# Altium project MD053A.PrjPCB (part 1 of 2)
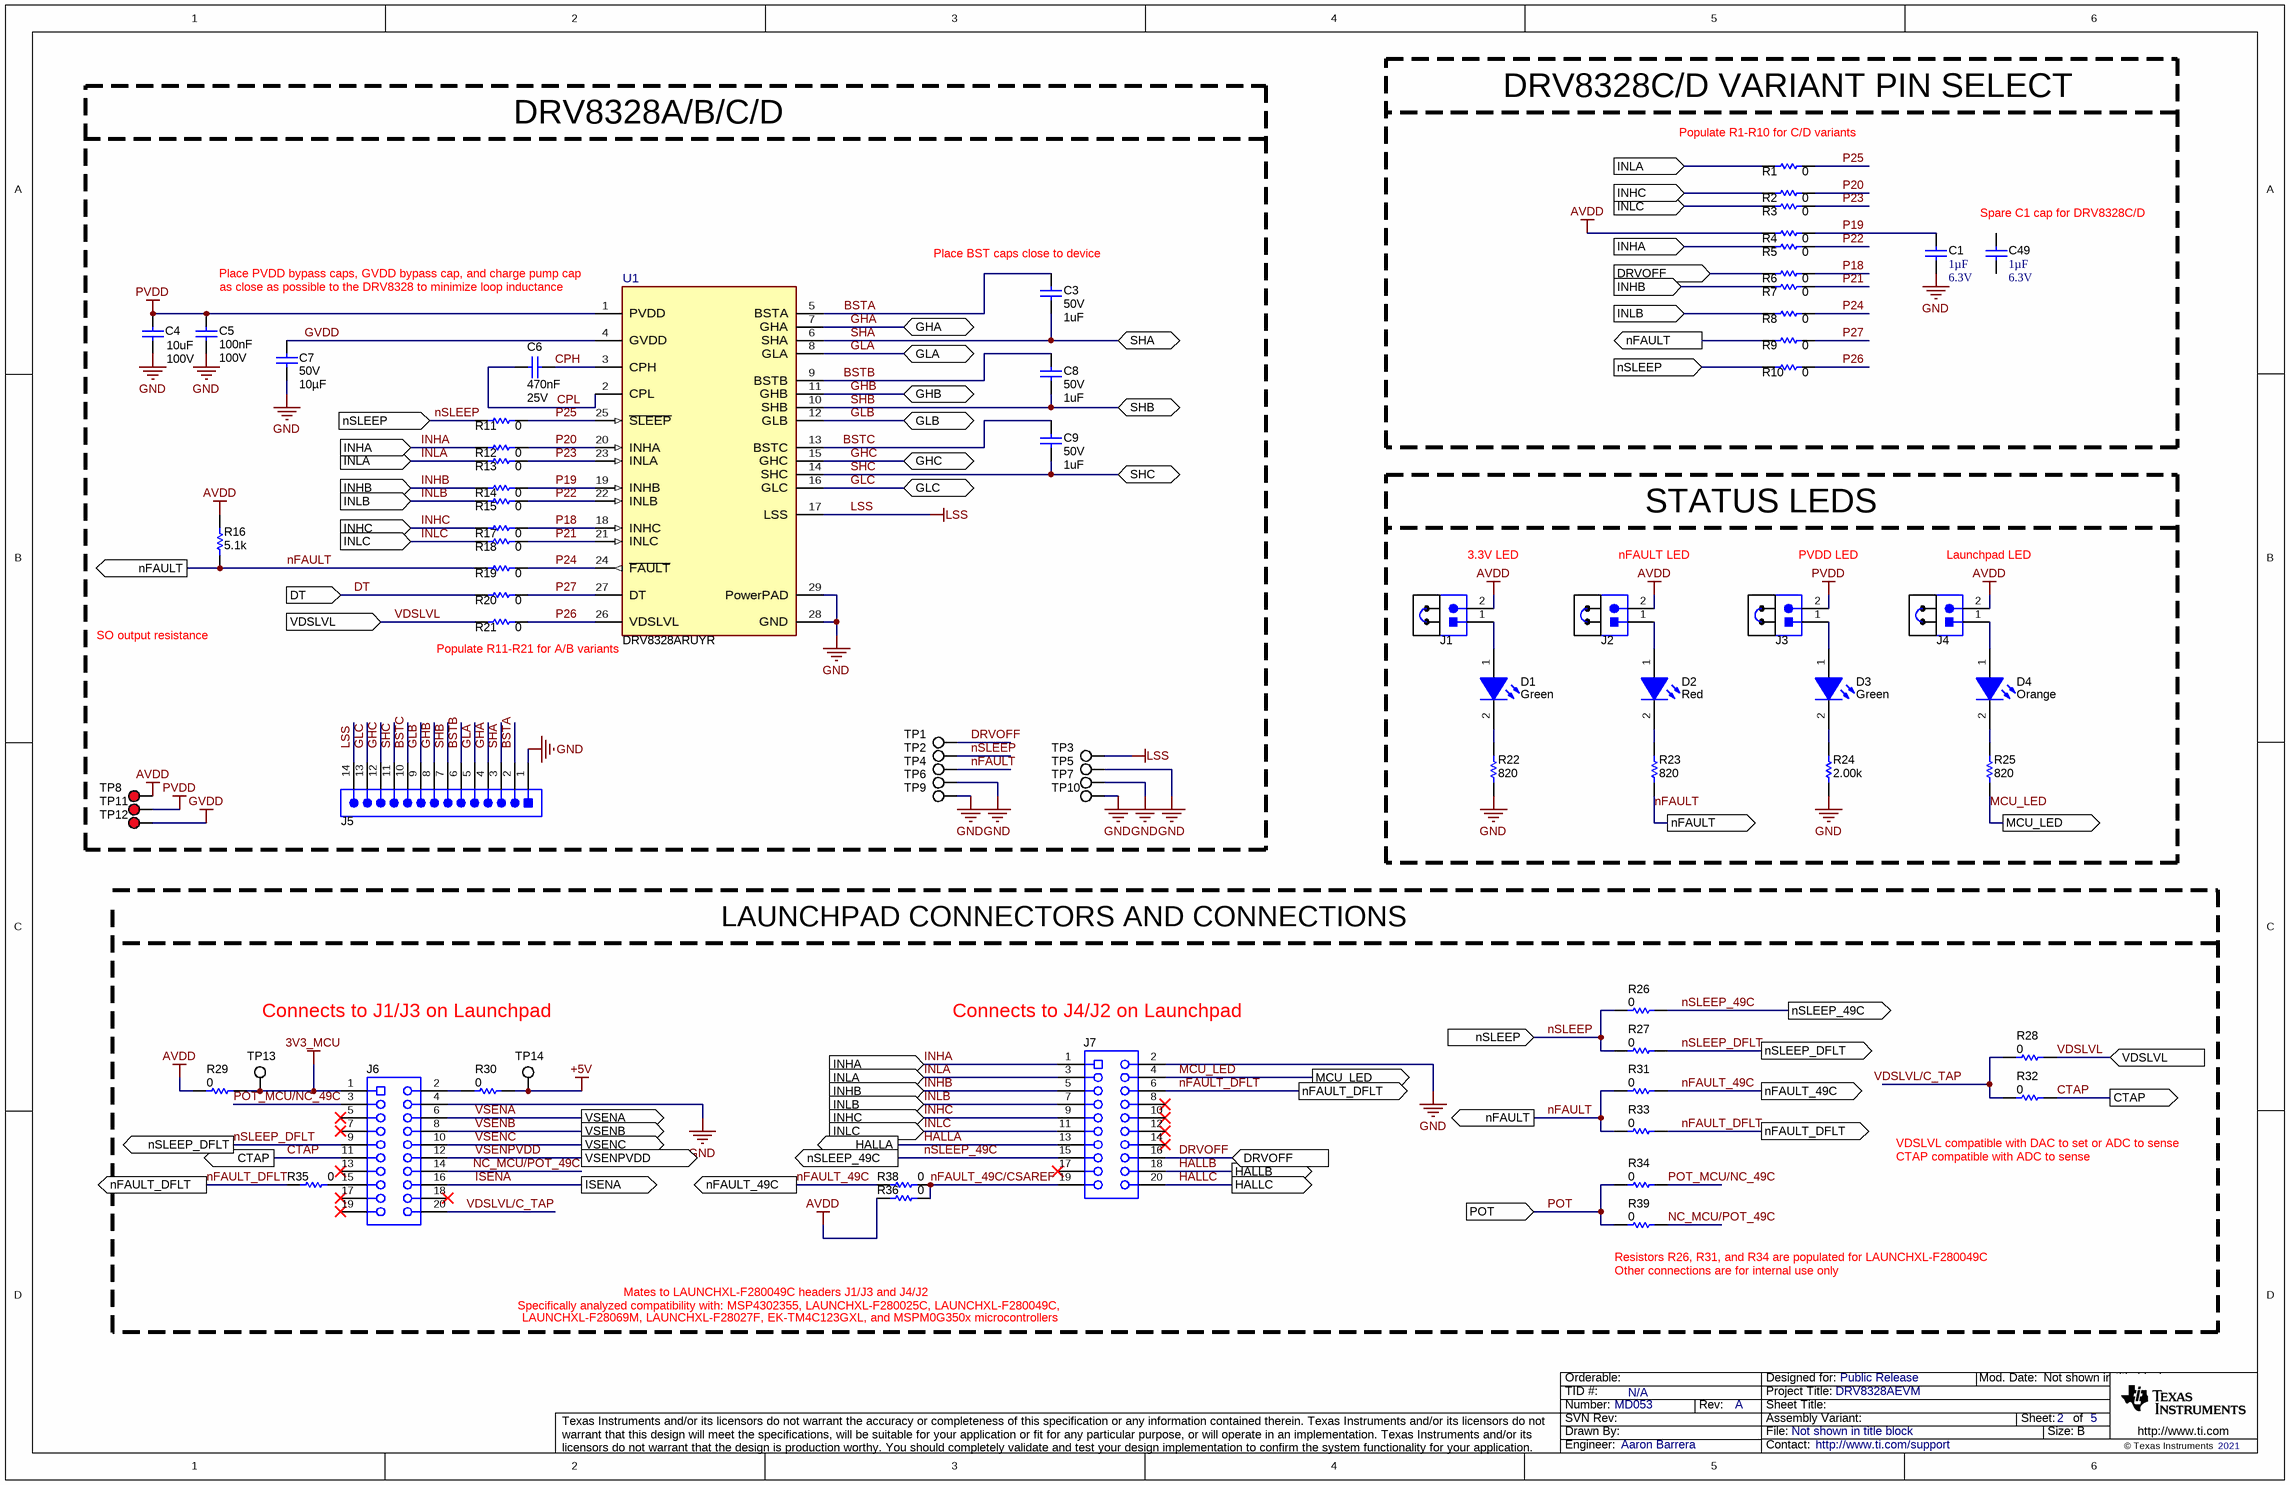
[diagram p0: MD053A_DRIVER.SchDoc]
CopyrightYear: 2021; PCB_Layout: Aaron Barrera; PCB_Rev: A; PRJ_Customer: Public Release; PRJ_Engineer: Aaron Barrera; PRJ_Number: MD053; PRJ_Title: DRV8328AEVM; SCH_Rev: A; TechSupport: http://www.ti.com/support; TID: N/A
5 sheets, 252 parts. Net scope: flat (ports and power ports of the same name join across sheets).
Board file: MD053A_PCB.PcbDoc
Sheets:
  MD053A_DRIVER.SchDoc
  MD053A_FETS_AND_POWER_STAGE.SchDoc
  MD053A_Hardware.SchDoc
  MD053A_LDO.SchDoc
  MD053A_POWER_AND_CONNECTORS.SchDoc

## Sheet MD053A_DRIVER.SchDoc
size 431 x 279 mm; Date: Not shown in title block; ApprovedBy: Not shown in title block; CheckedBy: Not shown in title block; Author: Not shown in title block; CompanyName: Not shown in title block; Engineer: Not shown in title block; Organization: Not shown in title block; Address1: Not shown in title block; Address2: Not shown in title block; Address3: Not shown in title block; Address4: Not shown in title block; DocumentNumber: 2; Revision: Use project parameter SCH_Rev; SheetNumber: 2; SheetTotal: 5; PageSetup: Record=PageOptions¦CenterHorizontal=True¦CenterVertical=True¦PrintScale=1.00¦XCorrection=1.00¦YCorrection=1.00¦PrintKind=0¦BorderSize=5000000¦LeftOffset=0¦BottomOffset=0¦Orientation=2¦PaperLength=1000¦PaperWidth=1000¦Scale=100¦PaperSource=15¦PrintQuality=600¦MediaType=1¦DitherType=10¦PaperKind=Letter¦PrintScaleMode=1

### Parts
C1  Cap_F: 1µF  VDC_V: 6.3V  [0603L]  (hidden comment: C0603C105K9RACAUTO)
C3  VDC_V: 50V  ValueDisplayed: 1uF  [0603L]  (hidden comment: C1608X5R1H105K080AB)
C4  VDC_V: 100V  ValueDisplayed: 10uF  [2220_280L]  (hidden comment: 22201C106MAT2A)
C5  Cap_F: 100nF  VDC_V: 100V  [0603L]  (hidden comment: GRM188R72A104KA35J)
C6  Cap_F: 470nF  VDC_V: 25V  [0603L]  (hidden comment: GRM188R71E474KA12D)
C7  VDC_V: 50V  ValueDisplayed: 10µF  [1206_190L]  (hidden comment: UMK316BBJ106KL-T)
C8  VDC_V: 50V  ValueDisplayed: 1uF  [0603L]  (hidden comment: C1608X5R1H105K080AB)
C9  VDC_V: 50V  ValueDisplayed: 1uF  [0603L]  (hidden comment: C1608X5R1H105K080AB)
C49  Cap_F: 1µF  VDC_V: 6.3V  [0603L]  (hidden comment: C0603C105K9RACAUTO)
D1  value Green  [LTST-C170KGKT_Green]  (hidden comment: LTST-C170KGKT)
D2  value Red  [LED_LTST-C170_Red]  (hidden comment: LTST-C170KRKT)
D3  value Green  [LTST-C170KGKT_Green]  (hidden comment: LTST-C170KGKT)
D4  value Orange  [LTST-C170KFKT_Orange]  (hidden comment: LTST-C170KFKT)
J1  TSW-102-07-G-S  [TSW-102-07-G-S]  (value not drawn)
J2  TSW-102-07-G-S  [TSW-102-07-G-S]  (value not drawn)
J3  TSW-102-07-G-S  [TSW-102-07-G-S]  (value not drawn)
J4  TSW-102-07-G-S  [TSW-102-07-G-S]  (value not drawn)
J5  TSW-114-07-G-S  [TSW-114-07-G-S]  (value not drawn)
J6  SSQ-110-03-G-D  [Samtec_SSQ-110-03-x-D]  (value not drawn)
J7  SSQ-110-03-G-D  [Samtec_SSQ-110-03-x-D]  (value not drawn)
R1  ValueDisplayed: 0  [0603L]  (hidden comment: ERJ-3GEY0R00V)
R2  ValueDisplayed: 0  [0603L]  (hidden comment: ERJ-3GEY0R00V)
R3  ValueDisplayed: 0  [0603L]  (hidden comment: ERJ-3GEY0R00V)
R4  ValueDisplayed: 0  [0603L]  (hidden comment: ERJ-3GEY0R00V)
R5  ValueDisplayed: 0  [0603L]  (hidden comment: ERJ-3GEY0R00V)
R6  ValueDisplayed: 0  [0603L]  (hidden comment: ERJ-3GEY0R00V)
R7  ValueDisplayed: 0  [0603L]  (hidden comment: ERJ-3GEY0R00V)
R8  ValueDisplayed: 0  [0603L]  (hidden comment: ERJ-3GEY0R00V)
R9  ValueDisplayed: 0  [0603L]  (hidden comment: ERJ-3GEY0R00V)
R10  ValueDisplayed: 0  [0603L]  (hidden comment: ERJ-3GEY0R00V)
R11  ValueDisplayed: 0  [0603L]  (hidden comment: ERJ-3GEY0R00V)
R12  ValueDisplayed: 0  [0603L]  (hidden comment: ERJ-3GEY0R00V)
R13  ValueDisplayed: 0  [0603L]  (hidden comment: ERJ-3GEY0R00V)
R14  ValueDisplayed: 0  [0603L]  (hidden comment: ERJ-3GEY0R00V)
R15  ValueDisplayed: 0  [0603L]  (hidden comment: ERJ-3GEY0R00V)
R16  ValueDisplayed: 5.1k  [0603L]  (hidden comment: CRCW06035K10JNEA)
R17  ValueDisplayed: 0  [0603L]  (hidden comment: ERJ-3GEY0R00V)
R18  ValueDisplayed: 0  [0603L]  (hidden comment: ERJ-3GEY0R00V)
R19  ValueDisplayed: 0  [0603L]  (hidden comment: ERJ-3GEY0R00V)
R20  ValueDisplayed: 0  [0603L]  (hidden comment: ERJ-3GEY0R00V)
R21  ValueDisplayed: 0  [0603L]  (hidden comment: ERJ-3GEY0R00V)
R22  ValueDisplayed: 820  [0603L]  (hidden comment: RC0603JR-07820RL)
R23  ValueDisplayed: 820  [0603L]  (hidden comment: RC0603JR-07820RL)
R24  ValueDisplayed: 2.00k  [0603L]  (hidden comment: RG1608P-202-B-T5)
R25  ValueDisplayed: 820  [0603L]  (hidden comment: RC0603JR-07820RL)
R26  ValueDisplayed: 0  [0603L]  (hidden comment: ERJ-3GEY0R00V)
R27  ValueDisplayed: 0  [0603L]  (hidden comment: ERJ-3GEY0R00V)
R28  ValueDisplayed: 0  [0603L]  (hidden comment: ERJ-3GEY0R00V)
R29  ValueDisplayed: 0  [0603L]  (hidden comment: ERJ-3GEY0R00V)
R30  ValueDisplayed: 0  [0603L]  (hidden comment: ERJ-3GEY0R00V)
R31  ValueDisplayed: 0  [0603L]  (hidden comment: ERJ-3GEY0R00V)
R32  ValueDisplayed: 0  [0603L]  (hidden comment: ERJ-3GEY0R00V)
R33  ValueDisplayed: 0  [0603L]  (hidden comment: ERJ-3GEY0R00V)
R34  ValueDisplayed: 0  [0603L]  (hidden comment: ERJ-3GEY0R00V)
R35  ValueDisplayed: 0  [0603L]  (hidden comment: ERJ-3GEY0R00V)
R36  ValueDisplayed: 0  [0603L]  (hidden comment: ERJ-3GEY0R00V)
R38  ValueDisplayed: 0  [0603L]  (hidden comment: ERJ-3GEY0R00V)
R39  ValueDisplayed: 0  [0603L]  (hidden comment: ERJ-3GEY0R00V)
SH-J1  SNT-100-BK-G  [SNT-100-BK-G]  (value not drawn)
SH-J2  SNT-100-BK-G  [SNT-100-BK-G]  (value not drawn)
SH-J3  SNT-100-BK-G  [SNT-100-BK-G]  (value not drawn)
SH-J4  SNT-100-BK-G  [SNT-100-BK-G]  (value not drawn)
TP1  DRVOFF  [Testpoint_Keystone_Miniature]  (value not drawn)
TP2  nSLEEP  [Testpoint_Keystone_Miniature]  (value not drawn)
TP3  LSS  [Testpoint_Keystone_Miniature]  (value not drawn)
TP4  nFAULT  [Testpoint_Keystone_Miniature]  (value not drawn)
TP5  GND  [Testpoint_Keystone_Miniature]  (value not drawn)
TP6  GND  [Testpoint_Keystone_Miniature]  (value not drawn)
TP7  GND  [Testpoint_Keystone_Miniature]  (value not drawn)
TP8  AVDD  [Keystone5000]  (value not drawn)
TP9  GND  [Testpoint_Keystone_Miniature]  (value not drawn)
TP10  GND  [Testpoint_Keystone_Miniature]  (value not drawn)
TP11  PVDD  [Keystone5000]  (value not drawn)
TP12  GVDD  [Keystone5000]  (value not drawn)
TP13  3V3_MCU  [Testpoint_Keystone_Miniature]  (value not drawn)
TP14  5V  [Testpoint_Keystone_Miniature]  (value not drawn)
U1  DRV8328ARUYR  [RUY0028A-MFG]

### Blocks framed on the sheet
DRV8328A/B/C/D: C3-C9 J5 R11-R21 TP1-TP12 U1
DRV8328C/D VARIANT PIN SELECT: C1 C49 R1-R10
STATUS LEDS: D1-D4 J1-J4 R22-R25 SH-J1-SH-J4

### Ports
CTAP (out), DRVOFF (in), DT (in), GHA (bidir), GHB (bidir), GHC (bidir), GLA (bidir), GLB (bidir), GLC (bidir), HALLA (out), HALLB (out), HALLC (out), INHA (in), INHB (in), INHC (in), INLA (in), INLB (in), INLC (in), ISENA (out), MCU_LED (out), nFAULT (out), nFAULT_49C (out), nFAULT_DFLT (out), nSLEEP (in), nSLEEP_49C (out), nSLEEP_DFLT (out), POT (in), SHA (bidir), SHB (bidir), SHC (bidir), VDSLVL (in), VSENA (out), VSENB (out), VSENC (out), VSENPVDD (out)

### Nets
3V3_MCU: J6.1 R29.2 TP13.1
+5V: R30.2 TP14.1
AVDD: J1.2 J2.2 J4.2 R4.1 R16.1 R29.1 R36.1 TP8.1
GND: C1.1 C4.2 C5.2 C7.2 J5.1 J6.4 J7.2 R22.1 R24.1 TP5.1 TP6.1 TP7.1 TP9.1 TP10.1 U1.28(GND) U1.29(PowerPAD)
GVDD: C7.1 TP12.1 U1.4(GVDD)
LSS: J5.14 TP3.1 U1.17(LSS)
PVDD: C4.1 C5.1 J3.2 TP11.1 U1.1(PVDD)
BSTA: C3.1 J5.2 U1.5(BSTA)
BSTB: C8.1 J5.6 U1.9(BSTB)
BSTC: C9.1 J5.10 U1.13(BSTC)
CPH: C6.1 U1.3(CPH)
CPL: C6.2 U1.2(CPL)
CTAP: J6.11 R32.2 ; port CTAP
DRVOFF: J7.16 R6.1 TP1.1 ; port DRVOFF
DT: R20.1 ; port DT
GHA: J5.4 U1.7(GHA) ; port GHA
GHB: J5.8 U1.11(GHB) ; port GHB
GHC: J5.12 U1.15(GHC) ; port GHC
GLA: J5.5 U1.8(GLA) ; port GLA
GLB: J5.9 U1.12(GLB) ; port GLB
GLC: J5.13 U1.16(GLC) ; port GLC
HALLA: J7.13 ; port HALLA
HALLB: J7.18 ; port HALLB
HALLC: J7.20 ; port HALLC
INHA: J7.1 R5.1 R12.1 ; port INHA
INHB: J7.5 R7.1 R14.1 ; port INHB
INHC: J7.9 R2.1 R17.1 ; port INHC
INLA: J7.3 R1.1 R13.1 ; port INLA
INLB: J7.7 R8.1 R15.1 ; port INLB
INLC: J7.11 R3.1 R18.1 ; port INLC
ISENA: J6.16 ; port ISENA
MCU_LED: J7.4 R25.1 ; port MCU_LED
NC_MCU/POT_49C: J6.14 R39.2
nFAULT: R9.1 R16.2 R19.1 R23.1 R31.1 R33.1 TP4.1 ; port nFAULT
nFAULT_49C: R31.2 R38.1 ; port nFAULT_49C
nFAULT_49C/CSAREF: J7.19 R36.2 R38.2
nFAULT_DFLT: J7.6 R33.2 R35.1 ; port nFAULT_DFLT
nSLEEP: R10.1 R11.1 R26.1 R27.1 TP2.1 ; port nSLEEP
nSLEEP_49C: J7.15 R26.2 ; port nSLEEP_49C
nSLEEP_DFLT: J6.9 R27.2 ; port nSLEEP_DFLT
P18: R6.2 R17.2 U1.18(INHC)
P19: C1.2 R4.2 R14.2 U1.19(INHB)
P20: R2.2 R12.2 U1.20(INHA)
P21: R7.2 R18.2 U1.21(INLC)
P22: R5.2 R15.2 U1.22(INLB)
P23: R3.2 R13.2 U1.23(INLA)
P24: R8.2 R19.2 U1.24(~{FAULT})
P25: R1.2 R11.2 U1.25(~{SLEEP})
P26: R10.2 R21.2 U1.26(VDSLVL)
P27: R9.2 R20.2 U1.27(DT)
POT: R34.1 R39.1 ; port POT
POT_MCU/NC_49C: J6.3 R34.2
SHA: C3.2 J5.3 U1.6(SHA) ; port SHA
SHB: C8.2 J5.7 U1.10(SHB) ; port SHB
SHC: C9.2 J5.11 U1.14(SHC) ; port SHC
VDSLVL: R21.1 R28.2 ; port VDSLVL
VDSLVL/C_TAP: J6.20 R28.1 R32.1
VSENA: J6.6 ; port VSENA
VSENB: J6.8 ; port VSENB
VSENC: J6.10 ; port VSENC
VSENPVDD: J6.12 ; port VSENPVDD
NetD1_1: D1.1(A) J1.1
NetD1_2: D1.2(K) R22.2
NetD2_1: D2.1(A) J2.1
NetD2_2: D2.2(K) R23.2
NetD3_1: D3.1(A) J3.1
NetD3_2: D3.2(K) R24.2
NetD4_1: D4.1(A) J4.1
NetD4_2: D4.2(K) R25.2
NetJ6_2: J6.2 R30.1
NetJ6_15: J6.15 R35.2

Not connected (* = marked no-connect by the designer): C49 1 2; J6 5* 7* 13* 17* 18* 19*; J7 8* 10* 12* 14* 17*

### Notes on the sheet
- (near R1) Populate R1-R10 for C/D variants
- (near C49) Spare C1 cap for DRV8328C/D
- as close as possible to the DRV8328 to minimize loop inductance
- Place PVDD bypass caps, GVDD bypass cap, and charge pump cap
- (near C3) Place BST caps close to device
- 3.3V LED
- nFAULT LED
- PVDD LED
- Launchpad LED
- SO output resistance
- Populate R11-R21 for A/B variants
- LAUNCHPAD CONNECTORS AND CONNECTIONS
- Connects to J1/J3 on Launchpad
- (near J7) Connects to J4/J2 on Launchpad
- (near R32) VDSLVL compatible with DAC to set or ADC to sense
- CTAP compatible with ADC to sense
- Mates to LAUNCHXL-F280049C headers J1/J3 and J4/J2
- Specifically analyzed compatibility with: MSP4302355, LAUNCHXL-F280025C, LAUNCHXL-F280049C,
- (near R39) Resistors R26, R31, and R34 are populated for LAUNCHXL-F280049C
- (near R39) Other connections are for internal use only
- LAUNCHXL-F28069M, LAUNCHXL-F28027F, EK-TM4C123GXL, and MSPM0G350x microcontrollers

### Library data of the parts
C1 C49 = CMP-0086190-1: CAP, CERM, 1 µF, 6.3 V,+/- 10%, X7R, AEC-Q200 Grade 1, 0603; Manufacturer: Kemet; SizeArea_mm2: 1.28; Cap_Case: 0603; SizeY_mm: 0.8; AEC Category: Q200; AEC Qualified: Y; TaMax_C: 125°C; SizeZ_mm: 1; SizeX_mm: 1.6; Polarized: N; Value: 1uF; SizeAreaWB_mm2: 4.68; TaMin_C: -55°C; U/M: EA
C3 C8 C9 = CMP-0007011-4: CAP, CERM, 1 uF, 50 V, +/- 10%, X5R, 0603; Manufacturer: TDK; TaMin_C: -55°C; ESR_ohm: 5.522m; Polarized: N; SizeAreaWB_mm2: 4.68; Value1: 0.005522 ohm; U/M: EA; Value: 1uF; TaMax_C: 85°C; SizeZ_mm: 1; SizeX_mm: 1.6; SizeY_mm: 0.8; Cap_Case: 0603; SizeArea_mm2: 1.28; Cap_F: 1µF; IRMS_A: 2.21617A; AEC Category: Q200
C4 = CMP-0009304-2: CAP, CERM, 10 uF, 100 V, +/- 20%, X7R, 2220; Manufacturer: AVX; TaMin_C: -55°C; Polarized: N; SizeAreaWB_mm2: 53.9; Value1: Unknown; U/M: EA; Value: 10uF; TaMax_C: 125°C; SizeZ_mm: 2.8; SizeX_mm: 5.7; SizeY_mm: 5; Cap_Case: 2220; SizeArea_mm2: 28.5; Cap_F: 10µF; AEC Category: Q200
C5 = CMP-0007470-5: CAP, CERM, 0.1 uF, 100 V, +/- 10%, X7R, 0603; Manufacturer: MuRata; TaMin_C: -55°C; Polarized: N; SizeAreaWB_mm2: 4.68; Value1: Unknown; U/M: EA; Value: 0.1uF; TaMax_C: 125°C; SizeZ_mm: 1; SizeX_mm: 1.6; SizeY_mm: 0.8; Cap_Case: 0603; SizeArea_mm2: 1.28; AEC Category: Q200
C6 = CMP-0007424-3: CAP, CERM, 0.47 uF, 25 V, +/- 10%, X7R, 0603; Manufacturer: MuRata; TaMin_C: -55°C; Polarized: N; SizeAreaWB_mm2: 4.68; Value1: Unknown; U/M: EA; Value: 0.47uF; TaMax_C: 125°C; SizeZ_mm: 1; SizeX_mm: 1.6; SizeY_mm: 0.8; Cap_Case: 0603; SizeArea_mm2: 1.28; AEC Category: Q200
C7 = CMP-0086153-1: CAP, CERM, 10 µF, 50 V,+/- 10%, X5R, 1206; Manufacturer: Taiyo Yuden; Polarized: N; SizeX_mm: 3.2; TaMax_C: 85°C; SizeY_mm: 1.6; AEC Category: Q200; SizeArea_mm2: 5.12; Cap_Case: 1206; SizeAreaWB_mm2: 10.92; TaMin_C: -55°C; SizeZ_mm: 1.9; U/M: EA; Value: 10uF
D1 D3 = CMP-0002888-2: LED, Green, SMD; Manufacturer: Lite-On; Io_A: 20mA; Value1: W; Vf_V: 2V; Type: AlInGaP
D2 = CMP-0002829-3: LED, Red, SMD; Manufacturer: Lite-On; Io_A: 20mA; SizeAreaWB_mm2: 6.75; Value1: W; SizeZ_mm: 1.2; SizeX_mm: 2; SizeY_mm: 1.25; Vf_V: 2V; SizeArea_mm2: 2.5; Type: AlInGaP
D4 = CMP-0002890-1: LED, Orange, SMD; Manufacturer: Lite-On; Io_A: 20mA; Value1: W; U/M: EA; Vf_V: 2V; Type: AlInGaP
J1-J4 = CMP-0075405-3: Header, 100mil, 2x1, Gold, TH; Manufacturer: Samtec; Current_A: 6.3A; Green_Lifecycle: Active; Pitch_mm: 2.54; Cert_CSA: Y; Cert_VDE: N; Green_REACh: Passed; Row_Count: 1; Gender: Male; Voltage_V: 550V
J5 = CMP-0075428-1: Header, 100mil, 14x1, Gold, TH; Manufacturer: Samtec; Pitch_mm: 2.54; Cert_VDE: N; Gender: Male; Cert_CSA: Y; Voltage_V: 550V; Green_REACh: Passed; Current_A: 6.3A; CT: False; Green_Lifecycle: Active; Row_Count: 1; CNHeader: True
J6 J7 = CMP-0075613-1: Receptacle, 2.54mm, 10x2, Gold, TH; Manufacturer: Samtec; Pitch_mm: 2.54; Cert_VDE: N; Gender: Female; Cert_CSA: Y; Current_A: 6.3A; Voltage_V: 550V; CT: True; Row_Count: 2; CompType: Socket Strip; CNHeader: False
R1-R15 R17-R21 R26-R36 R38 R39 = CMP-0025874-4: RES, 0, 5%, 0.1 W, AEC-Q200 Grade 0, 0603; Manufacturer: Panasonic; Power_W: 100mW; TempCo: 600 ppm/C; Value_Code: 0000; Value: 0; EIA_Code: E24; SizeX_mm: 1.6; SizeY_mm: 0.8; SizeZ_mm: 1; Value2: 0.1W; SizeArea_mm2: 1.28; AEC Qualified: Y; VDC_V: 50V; AEC Category: Q200; SizeAreaWB_mm2: 4.68
R16 = CMP-0025830-4: RES, 5.1 k, 5%, 0.1 W, AEC-Q200 Grade 0, 0603; Manufacturer: Vishay-Dale; Power_W: 100mW; TempCo: 200 ppm/C; Value_Code: 5k10; Value: 5.1k; EIA_Code: E24; SizeX_mm: 1.6; SizeY_mm: 0.8; SizeZ_mm: 1; Value2: 0.1W; SizeArea_mm2: 1.28; AEC Qualified: Y; VDC_V: 75V; AEC Category: Q200; AEC Grade: 0
R22 R23 R25 = CMP-0025941-5: RES, 820, 5%, 0.1 W, 0603; Manufacturer: Yageo; Power_W: 100mW; TempCo: 100 ppm/C; Value_Code: 820R; Value: 820; EIA_Code: E24; SizeX_mm: 1.6; SizeY_mm: 0.8; SizeZ_mm: 1; Value2: 0.1W; SizeArea_mm2: 1.28; AEC Qualified: N; VDC_V: 75V; AEC Category: Q200; SizeAreaWB_mm2: 4.68
R24 = CMP-0023463-3: RES, 2.00 k, 0.1%, 0.1 W, 0603; Manufacturer: Susumu Co Ltd; Power_W: 100mW; TempCo: 25 ppm/C; Value_Code: 2k00; U/M: EA; Value: 2.00k; EIA_Code: E192; Res_ohm: 2k; SizeX_mm: 1.6; SizeY_mm: 0.8; SizeZ_mm: 1; Value2: 0.1W; SizeArea_mm2: 1.28; VDC_V: 75V; AEC Category: Q200
SH-J1-SH-J4 = CMP-0003623-3: Shunt, 100mil, Gold plated, Black; Alternate PartNumber: 969102-0000-DA; Manufacturer: Samtec; Alternate Manufacturer: 3M; Value: 1x2
TP1-TP7 TP9 TP10 TP13 TP14 = CMP-0055152-1: Test Point, Miniature, SMT; Manufacturer: Keystone; CNHeader: FALSE; Green_Lifecycle: Active; Green_REACh: Passed; CT: TRUE
TP8 TP11 TP12 = CMP-0055137-1: Test Point, Miniature, Red, TH; PartNumber: 5000; Manufacturer: Keystone; ContactFinish: Silver; CNHeader: FALSE; CT: TRUE; Green_Lifecycle: Active; Green_REACh: Passed
U1 = CMP-0091885-1: Three-Phase BLDC Gate Driver; Manufacturer: Texas Instruments; AEC Qualified: No; Switching Frequency: 200kHz; Min Supply Voltage: 4.5V; Motor Type: Brushless DC; Nominal Supply Current: 4-5mA; Number Of Outputs: 3; SizeZ_mm: 0.8mm; TaMin_C: -40°C; TJmax_C: +150°C; Max Supply Voltage: 60V; TaMax_C: +125°C; Standoff Height: 0mm

## Sheet MD053A_FETS_AND_POWER_STAGE.SchDoc
size 431 x 279 mm; Date: Not shown in title block; ApprovedBy: Not shown in title block; CheckedBy: Not shown in title block; Author: Not shown in title block; CompanyName: Not shown in title block; Engineer: Not shown in title block; Organization: Not shown in title block; Address1: Not shown in title block; Address2: Not shown in title block; Address3: Not shown in title block; Address4: Not shown in title block; DocumentNumber: 3; Revision: Use project parameter SCH_Rev; SheetNumber: 3; SheetTotal: 5; PageSetup: Record=PageOptions¦CenterHorizontal=True¦CenterVertical=True¦PrintScale=1.00¦XCorrection=1.00¦YCorrection=1.00¦PrintKind=0¦BorderSize=5000000¦LeftOffset=0¦BottomOffset=0¦Orientation=2¦PaperLength=1000¦PaperWidth=1000¦Scale=100¦PaperSource=15¦PrintQuality=600¦MediaType=1¦DitherType=10¦PaperKind=Letter¦PrintScaleMode=1
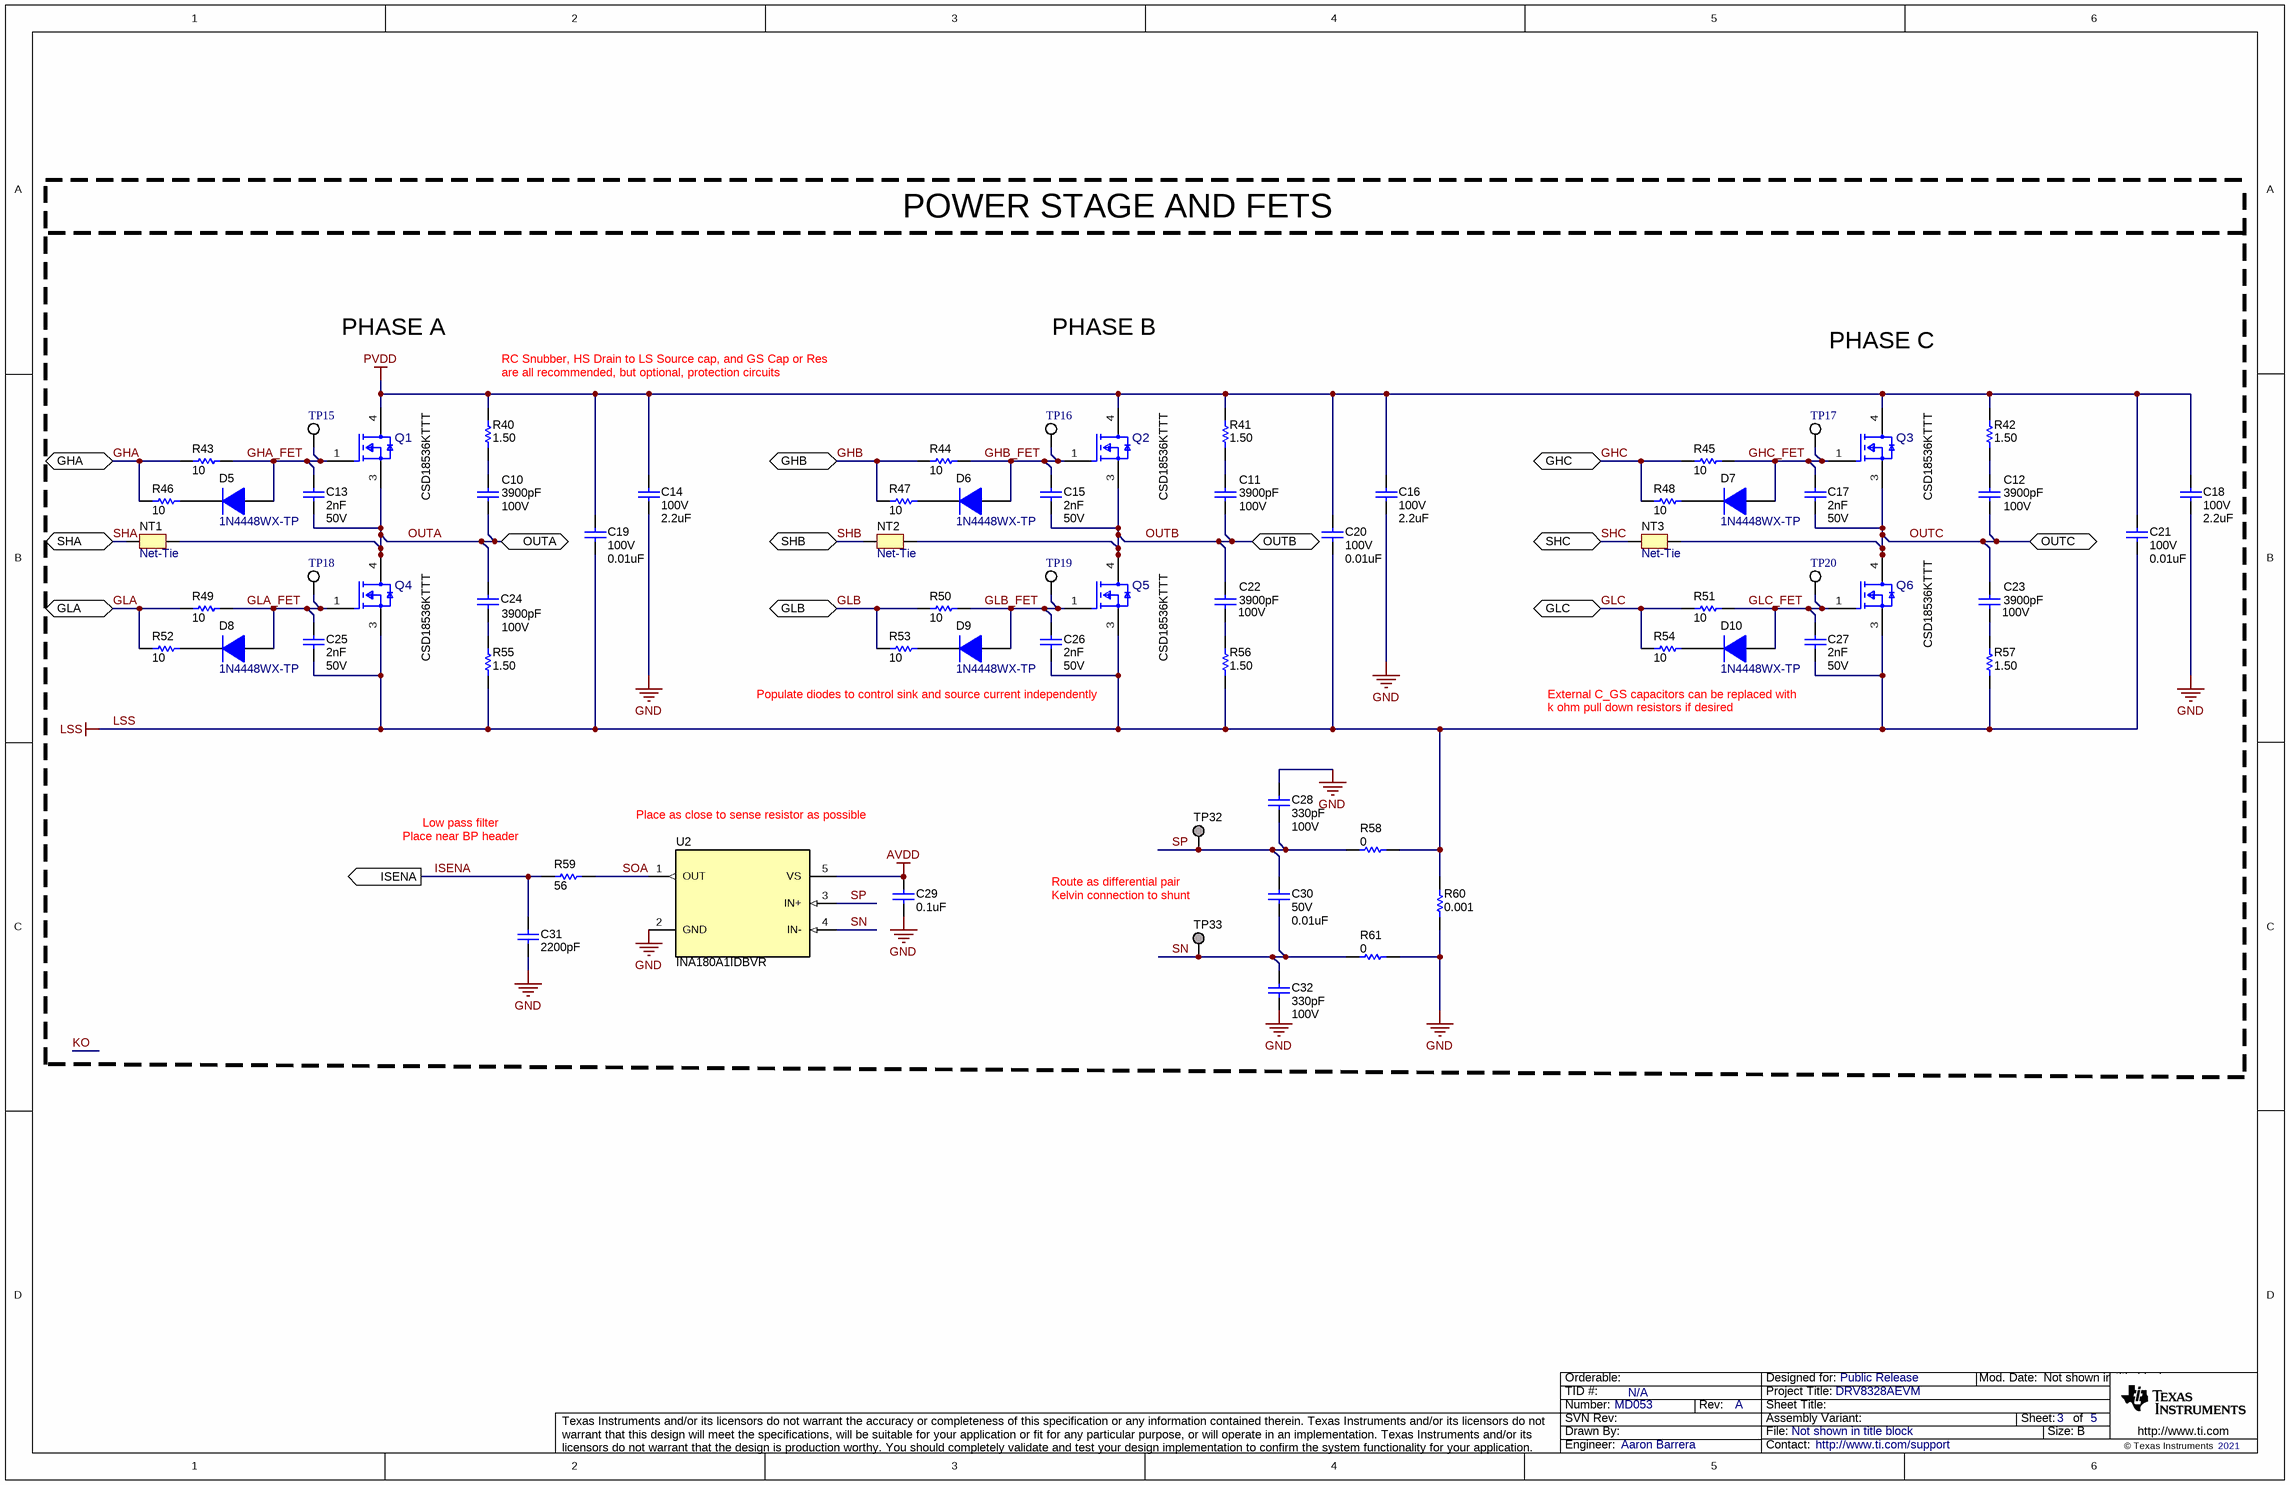
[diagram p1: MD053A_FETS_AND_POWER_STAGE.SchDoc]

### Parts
C10  VDC_V: 100V  ValueDisplayed: 3900pF  [1206L]  (hidden comment: 12061C392KAZ2A)
C11  VDC_V: 100V  ValueDisplayed: 3900pF  [1206L]  (hidden comment: 12061C392KAZ2A)
C12  VDC_V: 100V  ValueDisplayed: 3900pF  [1206L]  (hidden comment: 12061C392KAZ2A)
C13  Cap_F: 2nF  VDC_V: 50V  [0603L]  (hidden comment: GRM188R71H202KA01D)  (no BOM)
C14  VDC_V: 100V  ValueDisplayed: 2.2uF  [1210_210L]  (hidden comment: C1210C225K1RACTU)
C15  Cap_F: 2nF  VDC_V: 50V  [0603L]  (hidden comment: GRM188R71H202KA01D)  (no BOM)
C16  VDC_V: 100V  ValueDisplayed: 2.2uF  [1210_210L]  (hidden comment: C1210C225K1RACTU)
C17  Cap_F: 2nF  VDC_V: 50V  [0603L]  (hidden comment: GRM188R71H202KA01D)  (no BOM)
C18  VDC_V: 100V  ValueDisplayed: 2.2uF  [1210_210L]  (hidden comment: C1210C225K1RACTU)
C19  VDC_V: 100V  ValueDisplayed: 0.01uF  [0805L]  (hidden comment: 08051C103JAT2A)
C20  VDC_V: 100V  ValueDisplayed: 0.01uF  [0805L]  (hidden comment: 08051C103JAT2A)
C21  VDC_V: 100V  ValueDisplayed: 0.01uF  [0805L]  (hidden comment: 08051C103JAT2A)
C22  VDC_V: 100V  ValueDisplayed: 3900pF  [1206L]  (hidden comment: 12061C392KAZ2A)
C23  VDC_V: 100V  ValueDisplayed: 3900pF  [1206L]  (hidden comment: 12061C392KAZ2A)
C24  VDC_V: 100V  ValueDisplayed: 3900pF  [1206L]  (hidden comment: 12061C392KAZ2A)
C25  Cap_F: 2nF  VDC_V: 50V  [0603L]  (hidden comment: GRM188R71H202KA01D)  (no BOM)
C26  Cap_F: 2nF  VDC_V: 50V  [0603L]  (hidden comment: GRM188R71H202KA01D)  (no BOM)
C27  Cap_F: 2nF  VDC_V: 50V  [0603L]  (hidden comment: GRM188R71H202KA01D)  (no BOM)
C28  Cap_F: 330pF  VDC_V: 100V  [0603L]  (hidden comment: 06031C331KAT2A)
C29  ValueDisplayed: 0.1uF  [0603L]  (hidden comment: C0603C104J4RACTU)
C30  VDC_V: 50V  ValueDisplayed: 0.01uF  [0603L]  (hidden comment: C1608NP01H103J080AA)
C31  ValueDisplayed: 2200pF  [0603L]  (hidden comment: GRM188R71C222KA01D)
C32  Cap_F: 330pF  VDC_V: 100V  [0603L]  (hidden comment: 06031C331KAT2A)
D5  1N4448WX-TP  [SOD-323]
D6  1N4448WX-TP  [SOD-323]
D7  1N4448WX-TP  [SOD-323]
D8  1N4448WX-TP  [SOD-323]
D9  1N4448WX-TP  [SOD-323]
D10  1N4448WX-TP  [SOD-323]
NT1  Net-Tie  [NetTie_0603]  (net tie, no BOM)
NT2  Net-Tie  [NetTie_0603]  (net tie, no BOM)
NT3  Net-Tie  [NetTie_0603]  (net tie, no BOM)
Q1  CSD18536KTTT  [KTT0002A-MFG]
Q2  CSD18536KTTT  [KTT0002A-MFG]
Q3  CSD18536KTTT  [KTT0002A-MFG]
Q4  CSD18536KTTT  [KTT0002A-MFG]
Q5  CSD18536KTTT  [KTT0002A-MFG]
Q6  CSD18536KTTT  [KTT0002A-MFG]
R40  ValueDisplayed: 1.50  [1206L]  (hidden comment: CRCW12061R50FKEA)
R41  ValueDisplayed: 1.50  [1206L]  (hidden comment: CRCW12061R50FKEA)
R42  ValueDisplayed: 1.50  [1206L]  (hidden comment: CRCW12061R50FKEA)
R43  ValueDisplayed: 10  [0603L]  (hidden comment: CRCW060310R0JNEA)
R44  ValueDisplayed: 10  [0603L]  (hidden comment: CRCW060310R0JNEA)
R45  ValueDisplayed: 10  [0603L]  (hidden comment: CRCW060310R0JNEA)
R46  ValueDisplayed: 10  [0603L]  (hidden comment: CRCW060310R0JNEA)
R47  ValueDisplayed: 10  [0603L]  (hidden comment: CRCW060310R0JNEA)
R48  ValueDisplayed: 10  [0603L]  (hidden comment: CRCW060310R0JNEA)
R49  ValueDisplayed: 10  [0603L]  (hidden comment: CRCW060310R0JNEA)
R50  ValueDisplayed: 10  [0603L]  (hidden comment: CRCW060310R0JNEA)
R51  ValueDisplayed: 10  [0603L]  (hidden comment: CRCW060310R0JNEA)
R52  ValueDisplayed: 10  [0603L]  (hidden comment: CRCW060310R0JNEA)
R53  ValueDisplayed: 10  [0603L]  (hidden comment: CRCW060310R0JNEA)
R54  ValueDisplayed: 10  [0603L]  (hidden comment: CRCW060310R0JNEA)
R55  ValueDisplayed: 1.50  [1206L]  (hidden comment: CRCW12061R50FKEA)
R56  ValueDisplayed: 1.50  [1206L]  (hidden comment: CRCW12061R50FKEA)
R57  ValueDisplayed: 1.50  [1206L]  (hidden comment: CRCW12061R50FKEA)
R58  ValueDisplayed: 0  [0603L]  (hidden comment: ERJ-3GEY0R00V)
R59  value 56  [0603L]  (hidden comment: CRCW060356R0JNEA)
R60  ValueDisplayed: 0.001  [CSS2725_001]  (hidden comment: CSS2725FT1L00)
R61  ValueDisplayed: 0  [0603L]  (hidden comment: ERJ-3GEY0R00V)
TP15  GHA_FET  [Testpoint_Keystone_Miniature]  (value not drawn)
TP16  GHB_FET  [Testpoint_Keystone_Miniature]  (value not drawn)
TP17  GHC_FET  [Testpoint_Keystone_Miniature]  (value not drawn)
TP18  GLA_FET  [Testpoint_Keystone_Miniature]  (value not drawn)
TP19  GLB_FET  [Testpoint_Keystone_Miniature]  (value not drawn)
TP20  GLC_FET  [Testpoint_Keystone_Miniature]  (value not drawn)
TP32  SP  [TP_SM_1MM]  (value not drawn)  (no BOM)
TP33  SN  [TP_SM_1MM]  (value not drawn)  (no BOM)
U2  INA180A1IDBVR  [DBV0005A_N]

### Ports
GHA (bidir), GHB (bidir), GHC (bidir), GLA (bidir), GLB (bidir), GLC (bidir), ISENA (out), OUTA (bidir), OUTB (bidir), OUTC (bidir), SHA (bidir), SHB (bidir), SHC (bidir)

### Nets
AVDD: C29.1 U2.5(VS)
GND: C14.2 C16.2 C18.2 C28.1 C29.2 C31.2 C32.2 R60.1 R61.2 U2.2(GND)
LSS: C19.2 C20.2 C21.2 C25.2 C26.2 C27.2 Q4.3(Source) Q5.3(Source) Q6.3(Source) R55.1 R56.1 R57.1 R58.2 R60.2
PVDD: C14.1 C16.1 C18.1 C19.1 C20.1 C21.1 Q1.4(Drain) Q2.4(Drain) Q3.4(Drain) R40.1 R41.1 R42.1
GHA: R43.1 R46.1 ; port GHA
GHA_FET: C13.1 D5.2(A) Q1.1(Gate) R43.2 TP15.1
GHB: R44.1 R47.1 ; port GHB
GHB_FET: C15.1 D6.2(A) Q2.1(Gate) R44.2 TP16.1
GHC: R45.1 R48.1 ; port GHC
GHC_FET: C17.1 D7.2(A) Q3.1(Gate) R45.2 TP17.1
GLA: R49.1 R52.1 ; port GLA
GLA_FET: C25.1 D8.2(A) Q4.1(Gate) R49.2 TP18.1
GLB: R50.1 R53.1 ; port GLB
GLB_FET: C26.1 D9.2(A) Q5.1(Gate) R50.2 TP19.1
GLC: R51.1 R54.1 ; port GLC
GLC_FET: C27.1 D10.2(A) Q6.1(Gate) R51.2 TP20.1
ISENA: C31.1 R59.1 ; port ISENA
OUTA: C10.1 C13.2 C24.1 NT1.2 Q1.3(Source) Q4.4(Drain) ; port OUTA
OUTB: C11.1 C15.2 C22.1 NT2.2 Q2.3(Source) Q5.4(Drain) ; port OUTB
OUTC: C12.1 C17.2 C23.1 NT3.2 Q3.3(Source) Q6.4(Drain) ; port OUTC
SHA: NT1.1 ; port SHA
SHB: NT2.1 ; port SHB
SHC: NT3.1 ; port SHC
SN: C30.2 C32.1 R61.1 TP33.1 U2.4(IN-)
SOA: R59.2 U2.1(OUT)
SP: C28.2 C30.1 R58.1 TP32.1 U2.3(IN+)
NetC10_2: C10.2 R40.2
NetC11_2: C11.2 R41.2
NetC12_2: C12.2 R42.2
NetC22_2: C22.2 R56.2
NetC23_2: C23.2 R57.2
NetC24_2: C24.2 R55.2
NetD5_1: D5.1(K) R46.2
NetD6_1: D6.1(K) R47.2
NetD7_1: D7.1(K) R48.2
NetD8_1: D8.1(K) R52.2
NetD9_1: D9.1(K) R53.2
NetD10_1: D10.1(K) R54.2

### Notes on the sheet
- POWER STAGE AND FETS
- PHASE A
- RC Snubber, HS Drain to LS Source cap, and GS Cap or Res
- PHASE B
- PHASE C
- (near R40) are all recommended, but optional, protection circuits
- Populate diodes to control sink and source current independently
- External C_GS capacitors can be replaced with
- k ohm pull down resistors if desired
- Low pass filter
- (near R59) Place near BP header
- Place as close to sense resistor as possible
- Route as differential pair
- Kelvin connection to shunt

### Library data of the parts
C10-C12 C22-C24 = CMP-0008756-2: CAP CER 3900PF 100V X7R 1206; Manufacturer: AVX Corporation; TaMin_C: -55°C; Polarized: N; SizeAreaWB_mm2: 10.92; Value1: Unknown; U/M: EA; TaMax_C: 125°C; Tolerance_%: 10%; SizeZ_mm: 1.35; SizeX_mm: 3.2; SizeY_mm: 1.6; Cap_Case: 1206; SizeArea_mm2: 5.12; Cap_F: 3.9nF; AEC Category: Q200
C13 C15 C17 C25-C27 = CMP-0007441-5: CAP, CERM, 2000 pF, 50 V, +/- 10%, X7R, 0603; Manufacturer: MuRata; TaMin_C: -55°C; Polarized: N; SizeAreaWB_mm2: 4.68; Value1: Unknown; U/M: EA; Value: 2000pF; TaMax_C: 125°C; SizeZ_mm: 1; SizeX_mm: 1.6; SizeY_mm: 0.8; Cap_Case: 0603; SizeArea_mm2: 1.28; AEC Category: Q200
C14 C16 C18 = CMP-0009084-1: CAP, CERM, 2.2 uF, 100 V, +/- 10%, X7R, 1210; Manufacturer: Kemet; TaMin_C: -55°C; Polarized: N; SizeAreaWB_mm2: 14.7; Value1: Unknown; U/M: EA; Value: 2.2uF; TaMax_C: 125°C; SizeZ_mm: 2.1; SizeX_mm: 3.2; SizeY_mm: 2.5; Cap_Case: 1210; SizeArea_mm2: 8; CompType: Capacitor; Cap_F: 2.2µF; AEC Category: Q200
C19-C21 = CMP-0007542-2: CAP, CERM, 0.01 uF, 100 V, +/- 5%, X7R, 0805; Manufacturer: AVX; TaMin_C: -55°C; ESR_ohm: 0.078; Polarized: N; SizeAreaWB_mm2: 6.75; Value1: 0.078 ohm; U/M: EA; Value: 0.01uF; TaMax_C: 125°C; SizeZ_mm: 1.45; SizeX_mm: 2; SizeY_mm: 1.25; Cap_Case: 0805; SizeArea_mm2: 2.5; Cap_F: 10nF; AEC Category: Q200
C28 C32 = CMP-0006740-4: CAP, CERM, 330 pF, 100 V, +/- 10%, X7R, 0603; Manufacturer: AVX; TaMin_C: -55°C; ESR_ohm: 0.472; Polarized: N; SizeAreaWB_mm2: 4.68; Value1: 0.472 ohm; U/M: EA; Value: 330pF; TaMax_C: 125°C; SizeZ_mm: 1; SizeX_mm: 1.6; SizeY_mm: 0.8; Cap_Case: 0603; SizeArea_mm2: 1.28; AEC Category: Q200
C29 = CMP-0006857-4: CAP, CERM, 0.1 uF, 16 V, +/- 5%, X7R, 0603; Manufacturer: Kemet; Polarized: N; Value: 0.1uF; U/M: EA; Cap_F: 100nF; Value1: Unknown; VDC_V: 16V; TaMin_C: -55°C; TaMax_C: 125°C; Cap_Case: 0603; AEC Category: Q200; SizeArea_mm2: 1.28; SizeAreaWB_mm2: 4.68; SizeX_mm: 1.6; SizeY_mm: 0.8; SizeZ_mm: 1
C30 = CMP-0006998-4: CAP, CERM, 0.01 uF, 50 V, +/- 5%, C0G/NP0, 0603; Manufacturer: TDK; TaMin_C: -55°C; Polarized: N; SizeAreaWB_mm2: 4.68; Value1: Unknown; U/M: EA; Value: 0.01uF; TaMax_C: 150°C; SizeZ_mm: 1; SizeX_mm: 1.6; SizeY_mm: 0.8; Cap_Case: 0603; SizeArea_mm2: 1.28; Cap_F: 10nF; AEC Category: Q200
C31 = CMP-0007387-4: CAP, CERM, 2200 pF, 16 V, +/- 10%, X7R, 0603; Manufacturer: MuRata; Polarized: N; Value: 2200pF; U/M: EA; Cap_F: 2.2nF; Value1: Unknown; VDC_V: 16V; TaMin_C: -55°C; TaMax_C: 125°C; Cap_Case: 0603; SizeArea_mm2: 1.28; SizeAreaWB_mm2: 4.68; SizeX_mm: 1.6; SizeY_mm: 0.8; SizeZ_mm: 1; AEC Category: Q200
D5-D10 = CMP-0076911-2: Diode, Switching, 75 V, 0.25 A, SOD-323; Manufacturer: Micro Commercial Components; SizeArea_mm2: 3.645; TJmax_C: 150°C; Vr_V: 75V; SizeY_mm: 1.35; Value: 75V; SizeAreaWB_mm2: 8.695; Green_Lifecycle: Not Set; SizeX_mm: 2.7; AEC Category: Q101; Io_A: 250mA; Green_REACh: Incomplete; Value1: 0.25A; SizeZ_mm: 1.0
NT1-NT3 = CMP-0078142-2: Single point connection between nets.
Q1-Q6 = CMP-0092295-1: MOSFET 60-V, N channel NexFET power MOSFET, single D2PAK, 1.6 mOhm 3-DDPAK/TO-263 -55 to 175; Manufacturer: Texas Instruments; QgTyp_nC: 108nC @ 10V; Threshold Vgs Min: 1.4V; VdsMax_V: 1V; Standoff Height: 0mm; Rdson45_ohm: 1.3m; Reverse Recovery Time: 86ns; ChMode: False; Turn On Delay Time: 11ns; Typ Forward Diode Voltage: 0.9V; Transconductance: 312S; Threshold Vgs Max: 2.2V; Rthja Max: 62°C/W; Drain To Source Breakdown Voltage: 60V; Reverse Recovery Charge: 323nC; TJmax_C: +175°C; AEC Qualified: No; Power_W: 375W; Turn Off Delay Time: 24ns; Number Of Channels: 1; Vgs_V: 20V; SizeZ_mm: 4.95mm; Pulse Drain Current: 400A; IdsMax_A: 200A; Input Capacitace At Vds: 8790pF @ 30V
R40-R42 R55-R57 = CMP-0016763-3: RES, 1.50, 1%, 0.25 W, AEC-Q200 Grade 0, 1206; Manufacturer: Vishay-Dale; Power_W: 250mW; TempCo: 100 ppm/C; Value_Code: 1R50; Value: 1.50; EIA_Code: E96; Res_ohm: 1.5; SizeX_mm: 3.2; SizeY_mm: 1.6; SizeZ_mm: 1.35; Value2: 0.25W; SizeArea_mm2: 5.12; AEC Qualified: Y; VDC_V: 200V; AEC Category: Q200; AEC Grade: 0
R43-R54 = CMP-0025703-4: RES, 10, 5%, 0.1 W, AEC-Q200 Grade 0, 0603; Manufacturer: Vishay-Dale; Power_W: 100mW; TempCo: 200 ppm/C; Value_Code: 10R0; Value: 10; EIA_Code: E24; SizeX_mm: 1.6; SizeY_mm: 0.8; SizeZ_mm: 1; Value2: 0.1W; SizeArea_mm2: 1.28; AEC Qualified: Y; VDC_V: 75V; AEC Category: Q200; AEC Grade: 0
R58 R61 = CMP-0025874-4: as R1 on sheet MD053A_DRIVER
R59 = CMP-0025829-4: RES, 56, 5%, 0.1 W, AEC-Q200 Grade 0, 0603; Manufacturer: Vishay-Dale; Value_Code: 56R0; Power_W: 100mW; Value2: 0.1W; VDC_V: 75V; TempCo: 200 ppm/C; EIA_Code: E24; AEC Category: Q200; AEC Qualified: Y; AEC Grade: 0; SizeArea_mm2: 1.28; SizeX_mm: 1.6; SizeY_mm: 0.8; SizeZ_mm: 1
R60 = CMP-0015025-2: RES, 0.001, 1%, 4 W, RES_2725; Manufacturer: Stackpole Electronics Inc; Power_W: 4W; TempCo: 50 ppm/C; Value_Code: 1L000; U/M: EA; Value: 0.001; EIA_Code: E96; Res_ohm: 1m; AEC Category: Q200
TP15-TP20 = CMP-0055152-1: as TP1 on sheet MD053A_DRIVER
TP32 TP33 = CMP-0003825-1: 1mm Test Point, SMT; Manufacturer: Any
U2 = CMP-0013067-2: Low- and High-Side Measurement, Multichannel, Voltage Output, Current-Sense Amplifier, DBV0005A (SOT-5); Manufacturer: Texas Instruments; Alternate PartNumber: INA180A1IDBVT; SizeX_mm: 2.8; SizeY_mm: 2.9; CompType: IC; SizeZ_mm: 1.45; SizeArea_mm2: 8.12; SizeAreaWB_mm2: 14.82; U/M: EA

## Sheet MD053A_Hardware.SchDoc
size 431 x 279 mm; Date: Not shown in title block; ApprovedBy: Not shown in title block; CheckedBy: Not shown in title block; Author: Not shown in title block; CompanyName: Not shown in title block; Engineer: Not shown in title block; Organization: Not shown in title block; Address1: Not shown in title block; Address2: Not shown in title block; Address3: Not shown in title block; Address4: Not shown in title block; DocumentNumber: 5; Revision: Use project parameter SCH_Rev; SheetNumber: 5; SheetTotal: 5; PageSetup: Record=PageOptions¦CenterHorizontal=True¦CenterVertical=True¦PrintScale=1.00¦XCorrection=1.00¦YCorrection=1.00¦PrintKind=0¦BorderSize=5000000¦LeftOffset=0¦BottomOffset=0¦Orientation=2¦PaperLength=1000¦PaperWidth=1000¦Scale=100¦PaperSource=15¦PrintQuality=600¦MediaType=1¦DitherType=10¦PaperKind=Letter¦PrintScaleMode=1
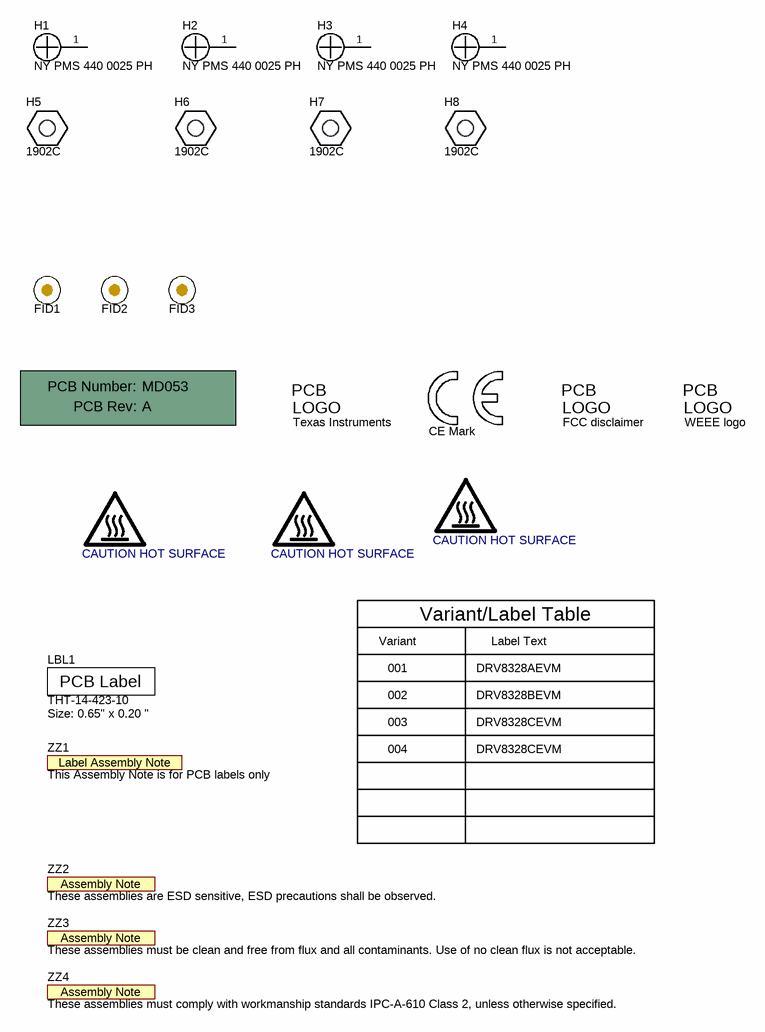
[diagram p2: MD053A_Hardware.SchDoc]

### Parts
!PCB1  Printed Circuit Board  (value not drawn)  (mechanical)
FID1  Fiducial  [Fiducial10-20]  (value not drawn)
FID2  Fiducial  [Fiducial10-20]  (value not drawn)
FID3  Fiducial  [Fiducial10-20]  (value not drawn)
H1  NY PMS 440 0025 PH  [NY PMS 440 0025 PH]
H2  NY PMS 440 0025 PH  [NY PMS 440 0025 PH]
H3  NY PMS 440 0025 PH  [NY PMS 440 0025 PH]
H4  NY PMS 440 0025 PH  [NY PMS 440 0025 PH]
H5  1902C  [Keystone_1902C]
H6  1902C  [Keystone_1902C]
H7  1902C  [Keystone_1902C]
H8  1902C  [Keystone_1902C]
LBL1  THT-14-423-10  Note: Size: 0.65" x 0.20 "  [Label_650x200]
Logo1  CE Mark  [CE_Mark_5mm]  (no BOM)
Logo2  Texas Instruments  [TI_Stacked_Overlay_Small]  (no BOM)
Logo3  FCC disclaimer  [FCC_disclaimer]  (no BOM)
Logo4  WEEE logo  [WEEE_Minimum]  (no BOM)
LOGO5  CAUTION HOT SURFACE  [IEC_HotSurface_Small]  (no BOM)
LOGO6  CAUTION HOT SURFACE  [IEC_HotSurface_Small]  (no BOM)
LOGO7  CAUTION HOT SURFACE  [IEC_HotSurface_Small]  (no BOM)
ZZ1  This Assembly Note is for PCB labels only  [AssemblyNoteLabel]  (no BOM)
ZZ2  These assemblies are ESD sensitive, ESD precautions shall be observed.  [AssemblyNote]  (no BOM)
ZZ3  These assemblies must be clean and free from flux and all contaminants. Use of no clean flux is not acceptable.  [AssemblyNote]  (no BOM)
ZZ4  These assemblies must comply with workmanship standards IPC-A-610 Class 2, unless otherwise specified.  [AssemblyNote]  (no BOM)

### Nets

Not connected (* = marked no-connect by the designer): H1 1; H2 1; H3 1; H4 1

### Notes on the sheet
- Variant
- Variant/Label Table
- Label Text
- 001
- 002
- DRV8328AEVM
- DRV8328BEVM
- 003
- 004
- DRV8328CEVM

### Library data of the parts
!PCB1 = CMP-0003618-2: Manufacturer: Any; PartNumber: MD053
FID1-FID3 = CMP-0077181-1: Fiducial mark.  There is nothing to buy or mount.
H1-H4 = CMP-0003617-1: Machine Screw, Round, #4-40 x 1/4, Nylon, Philips panhead; Manufacturer: B&F Fastener Supply; CompType: Hardware
H5-H8 = CMP-0003610-1: Standoff, Hex, 0.5"L #4-40 Nylon; Manufacturer: Keystone; CompType: Hardware
LBL1 = CMP-0003625-1: Thermal Transfer Printable Labels, 0.650" W x 0.200" H - 10,000 per roll; Manufacturer: Brady; CompType: Label
Logo1 = CMP-0074844-1: SymbolCreator: a0412235
Logo2 = CMP-0074838-1: Texas Instrument Corporate Signature; SymbolCreator: a0412235; Lib Reference: TI_Logo; Library Reference: Logo
Logo3 = CMP-0074847-1: FCC_disclaimer; Library Reference: Logo
Logo4 = CMP-0074769-1
LOGO5-LOGO7 = CMP-0074837-1: IEC 61010-1 Hot Surface Warning; SymbolCreator: a0412235
ZZ1 = CMP-0003616-3
ZZ2 = CMP-0077236-1
ZZ3 = CMP-0077237-1
ZZ4 = CMP-0077238-1

## Sheet MD053A_LDO.SchDoc
size A2; Date: Not shown in title block; ApprovedBy: Not shown in title block; CheckedBy: Not shown in title block; Author: Not shown in title block; CompanyName: Not shown in title block; Engineer: Not shown in title block; Organization: Not shown in title block; Address1: Not shown in title block; Address2: Not shown in title block; Address3: Not shown in title block; Address4: Not shown in title block; DocumentNumber: 2; Revision: Use project parameter SCH_Rev; SheetNumber: 2; SheetTotal: 3; PageSetup: Record=PageOptions¦CenterHorizontal=True¦CenterVertical=True¦PrintScale=1.00¦XCorrection=1.00¦YCorrection=1.00¦PrintKind=0¦BorderSize=5000000¦LeftOffset=0¦BottomOffset=0¦Orientation=2¦PaperLength=1000¦PaperWidth=1000¦Scale=100¦PaperSource=15¦PrintQuality=600¦MediaType=1¦DitherType=10¦PaperKind=Letter¦PrintScaleMode=1
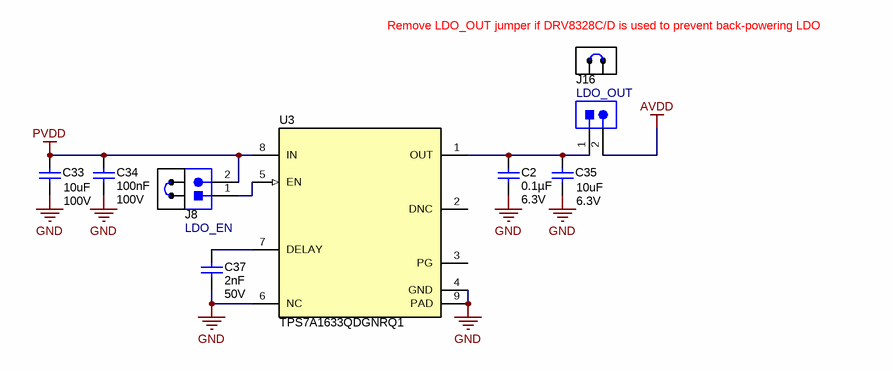
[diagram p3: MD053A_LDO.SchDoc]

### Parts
C2  ValueDisplayed: 0.1µF  VDC_V: 6.3V  [0603L]  (hidden comment: C0603C104K9PAC7867)
C33  VDC_V: 100V  ValueDisplayed: 10uF  [2220_280L]  (hidden comment: 22201C106MAT2A)
C34  Cap_F: 100nF  VDC_V: 100V  [0603L]  (hidden comment: GRM188R72A104KA35J)
C35  VDC_V: 6.3V  ValueDisplayed: 10uF  [0603L]  (hidden comment: C0603C106M9PACTU)
C37  Cap_F: 2nF  VDC_V: 50V  [0603L]  (hidden comment: GRM188R71H202KA01D)  (no BOM)
J8  LDO_EN  [TSW-102-07-G-S]
J16  LDO_OUT  [TSW-102-07-G-S]
SH-J5  SNT-100-BK-G  [SNT-100-BK-G]  (value not drawn)
SH-J9  SNT-100-BK-G  [SNT-100-BK-G]  (value not drawn)
U3  TPS7A1633QDGNRQ1  [DGN0008B_N]

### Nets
AVDD: J16.2
GND: C2.2 C33.2 C34.2 C35.2 C37.2 U3.4(GND) U3.6(NC) U3.9(PAD)
PVDD: C33.1 C34.1 J8.2 U3.8(IN)
NetC2_1: C2.1 C35.1 J16.1 U3.1(OUT)
NetC37_1: C37.1 U3.7(DELAY)
NetJ8_1: J8.1 U3.5(EN)

Not connected (* = marked no-connect by the designer): U3 2(DNC) 3(PG)

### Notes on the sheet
- (near SH-J9) Remove LDO_OUT jumper if DRV8328C/D is used to prevent back-powering LDO

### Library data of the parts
C2 = CMP-0085846-1: CAP, CERM, 0.1 µF, 6.3 V,+/- 10%, X5R, 0603; Manufacturer: Kemet; SizeAreaWB_mm2: 4.68; Cap_Case: 0603; SizeArea_mm2: 1.28; SizeZ_mm: 1; Polarized: N; Cap_F: 100nF; TaMin_C: -55°C; AEC Category: Q200; SizeX_mm: 1.6; Value: 0.1uF; U/M: EA; SizeY_mm: 0.8; TaMax_C: 85°C
C33 = CMP-0009304-2: as C4 on sheet MD053A_DRIVER
C34 = CMP-0007470-5: as C5 on sheet MD053A_DRIVER
C35 = CMP-0006872-5: CAP, CERM, 10 uF, 6.3 V, +/- 20%, X5R, 0603; Manufacturer: Kemet; TaMin_C: -55°C; ESR_ohm: 4m; Polarized: N; SizeAreaWB_mm2: 4.68; Value1: 0.004 ohm; U/M: EA; Value: 10uF; TaMax_C: 85°C; SizeZ_mm: 1; SizeX_mm: 1.6; SizeY_mm: 0.8; Cap_Case: 0603; SizeArea_mm2: 1.28; Cap_F: 10µF; IRMS_A: 8.9A; AEC Category: Q200
C37 = CMP-0007441-5: as C13 on sheet MD053A_FETS_AND_POWER_STAGE
J8 J16 = CMP-0075405-3: as J1 on sheet MD053A_DRIVER
SH-J5 SH-J9 = CMP-0003623-3: as SH-J1 on sheet MD053A_DRIVER
U3 = CMP-0066910-3: Automotive 60V, 5uA IQ Low-Dropout 100mA Linear Regulator with Enable and Power Good, DGN0008B (VSSOP-8); Alternate Manufacturer: Texas Instruments; SizeAreaWB_mm2: 23.6; SizeZ_mm: 1.1; SizeX_mm: 4.9; SizeY_mm: 3.0; SizeArea_mm2: 14.7; CompType: IC; AEC Category: Q200; AEC Qualified: Y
